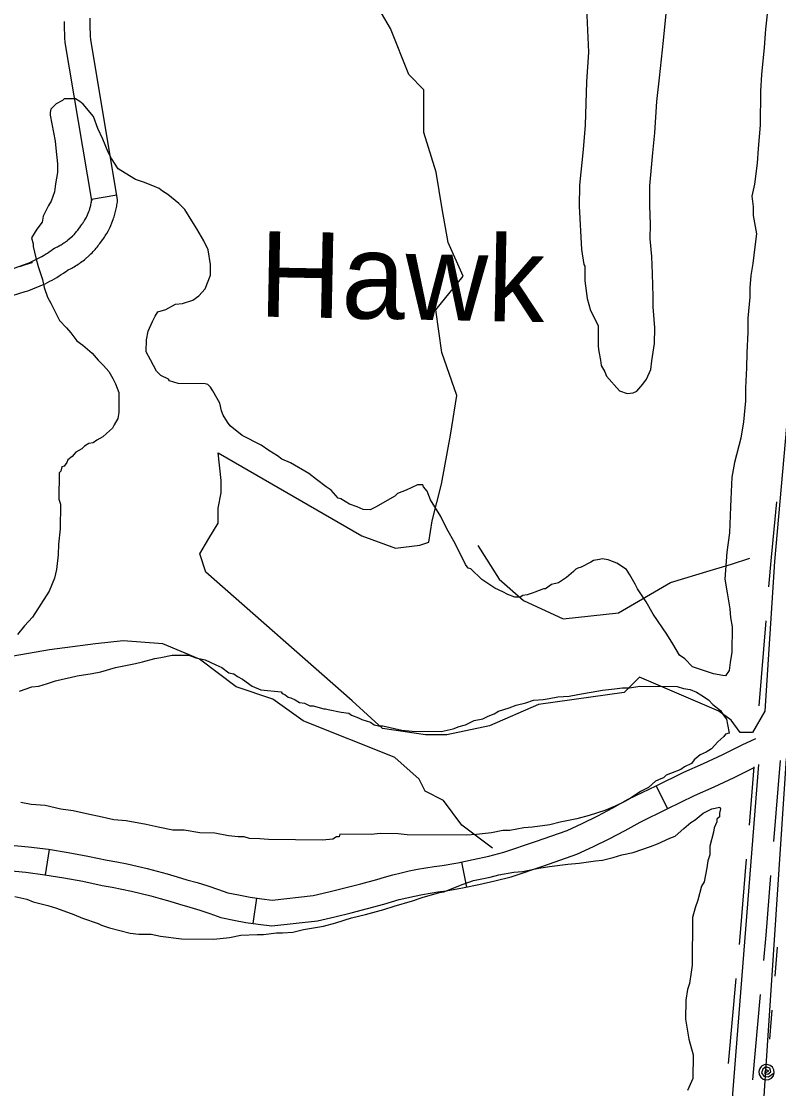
# Model space of a CAD drawing. Extents: x 3172231 to 3210228, y 940198 to 965780.
# Drawn here: x 3181959 to 3182846, y 958356 to 959605 of the extents above; entities that cross this region are included whole.
import ezdxf

# ---------------------------------------------------------------- set-up
doc = ezdxf.new("R2010")
doc.units = 0
for name, color, linetype in [('V-BLDG-IDEN', 7, 'Continuous'), ('V-ROAD-CNTR', 7, 'Continuous'), ('V-SITE-VEGE', 7, 'Continuous'), ('V-TOPO-SHOR', 7, 'Continuous'), ('V-UTIL-LINE', 7, 'Continuous')]:
    doc.layers.add(name, color=color, linetype=linetype)

msp = doc.modelspace()

# ---------------------------------------------------------------- linework, layer by layer
at = {"layer": 'V-ROAD-CNTR'}
for p, q in [((3182041.555, 959396.9), (3182071.146, 959401.841)), ((3182823.248, 958803.608), (3182831.446, 958903.271)), ((3182811.771, 958664.079), (3182817.388, 958732.364)), ((3182840.302, 958644.992), (3182848.114, 958739.96)), ((3182702.78, 958710.235), (3182715.953, 958683.282)), ((3181991.991, 958635.663), (3181987.327, 958606.028)), ((3182474.638, 958620.929), (3182480.562, 958591.52)), ((3182234.916, 958578.761), (3182230.422, 958549.099)), ((3182787.42, 958385.143), (3182796.528, 958484.727)), ((3182815.8, 958366.069), (3182824.908, 958465.653))]:
    msp.add_line(p, q, dxfattribs=at)
for points in [[(3181941.799, 959281.782), (3181964.107, 959288.718), (3181967.069, 959289.698), (3181970.006, 959290.727), (3181972.926, 959291.806), (3181975.83, 959292.938), (3181978.773, 959294.145), (3181984.349, 959296.605), (3181987.229, 959297.965), (3181990.019, 959299.345), (3181992.783, 959300.771), (3181995.53, 959302.249), (3181998.243, 959303.772), (3182000.934, 959305.341), (3182003.597, 959306.962), (3182006.232, 959308.626), (3182008.834, 959310.337), (3182011.403, 959312.088), (3182013.915, 959313.865), (3182013.447, 959313.525), (3182013.656, 959313.624), (3182015.243, 959314.407), (3182016.819, 959315.22), (3182018.383, 959316.062), (3182019.927, 959316.929), (3182021.457, 959317.823), (3182022.972, 959318.745), (3182024.462, 959319.687), (3182025.936, 959320.654), (3182027.405, 959321.654), (3182028.861, 959322.686), (3182030.285, 959323.733), (3182031.69, 959324.803), (3182033.288, 959326.066), (3182039.55, 959331.565), (3182041.001, 959332.984), (3182042.24, 959334.235), (3182043.466, 959335.517), (3182044.671, 959336.823), (3182045.854, 959338.15), (3182047.004, 959339.49), (3182048.129, 959340.844), (3182049.239, 959342.228), (3182050.327, 959343.634), (3182051.384, 959345.054), (3182052.414, 959346.486), (3182053.404, 959347.915), (3182053.321, 959347.792), (3182054.862, 959349.856), (3182055.842, 959351.245), (3182056.755, 959352.589), (3182057.652, 959353.957), (3182058.517, 959355.332), (3182059.394, 959356.774), (3182060.953, 959359.504), (3182061.755, 959360.999), (3182062.5, 959362.447), (3182063.337, 959364.145), (3182066.347, 959371.159), (3182067.001, 959372.932), (3182067.539, 959374.473), (3182068.05, 959376.029), (3182068.531, 959377.583), (3182068.984, 959379.137), (3182069.416, 959380.716), (3182069.818, 959382.307), (3182070.205, 959383.956), (3182070.843, 959387.024), (3182071.141, 959388.687), (3182071.405, 959390.296), (3182071.638, 959391.917), (3182071.835, 959393.472), (3182072.127, 959395.966), (3182040.741, 959583.943), (3182040.5, 959587.59), (3182040.294, 959591.859), (3182040.161, 959596.132), (3182040.102, 959600.401), (3182040.121, 959604.801)], [(3181957.397, 959318.098), (3181959.846, 959318.955), (3181962.276, 959319.854), (3181964.688, 959320.794), (3181967.025, 959321.753), (3181971.889, 959323.897), (3181974.171, 959324.975), (3181976.491, 959326.123), (3181978.799, 959327.313), (3181981.078, 959328.539), (3181983.341, 959329.81), (3181985.578, 959331.115), (3181987.789, 959332.46), (3181989.98, 959333.844), (3181992.144, 959335.267), (3181994.291, 959336.73), (3181996.435, 959338.247), (3181998.087, 959339.447), (3182000.606, 959340.638), (3182001.727, 959341.191), (3182002.833, 959341.762), (3182003.927, 959342.35), (3182005.013, 959342.961), (3182006.093, 959343.591), (3182007.154, 959344.237), (3182008.216, 959344.909), (3182009.264, 959345.596), (3182010.291, 959346.296), (3182011.301, 959347.01), (3182012.309, 959347.753), (3182013.304, 959348.509), (3182014.074, 959349.118), (3182019.15, 959353.577), (3182019.857, 959354.268), (3182020.744, 959355.163), (3182021.602, 959356.059), (3182022.445, 959356.973), (3182023.27, 959357.9), (3182024.086, 959358.85), (3182024.891, 959359.818), (3182025.669, 959360.788), (3182026.427, 959361.77), (3182027.174, 959362.772), (3182027.904, 959363.788), (3182028.634, 959364.841), (3182028.845, 959365.154), (3182030.58, 959367.48), (3182031.178, 959368.327), (3182031.805, 959369.249), (3182032.41, 959370.171), (3182033.003, 959371.114), (3182033.548, 959372.01), (3182034.705, 959374.036), (3182035.197, 959374.953), (3182035.706, 959375.943), (3182036.081, 959376.703), (3182038.469, 959382.267), (3182038.761, 959383.062), (3182039.125, 959384.105), (3182039.47, 959385.151), (3182039.799, 959386.215), (3182040.112, 959387.289), (3182040.402, 959388.352), (3182040.672, 959389.415), (3182040.911, 959390.434), (3182041.387, 959392.728), (3182041.573, 959393.759), (3182041.751, 959394.854), (3182041.908, 959395.941), (3182042.055, 959397.1), (3182041.835, 959395.222), (3182010.905, 959580.475), (3182010.548, 959585.876), (3182010.316, 959590.669), (3182010.167, 959595.46), (3182010.102, 959600.259), (3182010.121, 959604.927)], [(3182040.118, 959604.546), (3182040.208, 959608.816)], [(3181946.867, 959314.473), (3181971.799, 959323.696), (3181971.799, 959322.526), (3181954.939, 959317.284)], [(3182834.725, 958943.137), (3182837.566, 958977.674), (3182843.847, 959042.717)], [(3181929.836, 958642.409), (3181967.912, 958638.792), (3181991.21, 958635.786), (3182014.381, 958632.139), (3182037.44, 958627.855), (3182059.891, 958623.038), (3182071.391, 958621.01), (3182083.263, 958618.686), (3182095.092, 958616.141), (3182106.875, 958613.379), (3182118.605, 958610.394), (3182130.275, 958607.194), (3182141.88, 958603.777), (3182153.049, 958600.264), (3182165.214, 958596.865), (3182177.709, 958593.042), (3182190.104, 958588.911), (3182201.2, 958584.907), (3182213.799, 958582.322), (3182227.339, 958579.909), (3182240.936, 958577.849), (3182253.019, 958576.337), (3182301.27, 958581.648), (3182319.333, 958585.891), (3182338.13, 958590.561), (3182356.866, 958595.471), (3182375.509, 958600.613), (3182384.749, 958603.323), (3182394.324, 958605.907), (3182403.958, 958608.285), (3182413.645, 958610.453), (3182423.374, 958612.41), (3182433.143, 958614.155), (3182442.942, 958615.686), (3182452.319, 958616.943), (3182470.466, 958620.089), (3182488.615, 958623.744), (3182506.653, 958627.89), (3182524.255, 958632.444), (3182561.547, 958644.938), (3182598.488, 958657.913), (3182616.228, 958666.07), (3182634.205, 958674.918), (3182651.939, 958684.235), (3182669.974, 958694.327), (3182702.53, 958710.113), (3182734.89, 958725.928), (3182758.166, 958736.258), (3182780.834, 958746.888), (3182803.529, 958758.11), (3182819.534, 958765.691)], [(3181926.768, 958612.565), (3181964.574, 958608.974), (3181986.958, 958606.086), (3182009.307, 958602.569), (3182031.552, 958598.435), (3182054.137, 958593.59), (3182065.903, 958591.514), (3182077.227, 958589.298), (3182088.512, 958586.871), (3182099.751, 958584.235), (3182110.939, 958581.388), (3182122.071, 958578.336), (3182133.142, 958575.077), (3182144.509, 958571.5), (3182156.788, 958568.071), (3182168.575, 958564.464), (3182180.268, 958560.567), (3182193.052, 958555.953), (3182208.151, 958552.856), (3182222.459, 958550.305), (3182236.826, 958548.129), (3182252.795, 958546.131), (3182306.36, 958552.028), (3182326.381, 958556.729), (3182345.55, 958561.493), (3182364.656, 958566.499), (3182383.721, 958571.757), (3182392.881, 958574.445), (3182401.828, 958576.859), (3182410.83, 958579.081), (3182419.879, 958581.107), (3182428.97, 958582.934), (3182438.097, 958584.565), (3182447.25, 958585.996), (3182456.875, 958587.285), (3182475.992, 958590.599), (3182494.937, 958594.416), (3182513.771, 958598.744), (3182532.787, 958603.664), (3182571.283, 958616.562), (3182609.75, 958630.071), (3182629.12, 958638.978), (3182647.807, 958648.176), (3182666.243, 958657.861), (3182683.856, 958667.717), (3182715.66, 958683.139), (3182747.566, 958698.732), (3182770.62, 958708.964), (3182793.852, 958719.858), (3182816.599, 958731.106), (3182817.142, 958731.363)], [(3182800.171, 958524.561), (3182801.402, 958538.025), (3182808.492, 958624.214)], [(3182828.552, 958505.487), (3182831.29, 958535.429), (3182837.023, 958605.126)]]:
    msp.add_lwpolyline(points, dxfattribs=at)
at = {"layer": 'V-SITE-VEGE'}
for points in [[(3182619.192, 959663.857), (3182623.434, 959569.057), (3182621.085, 959534.436), (3182619.608, 959483.502), (3182617.312, 959454.992), (3182612.862, 959413.256), (3182612.641, 959388.802), (3182615.24, 959337.834), (3182618.14, 959320.487), (3182619.141, 959318.437), (3182618.987, 959301.117), (3182621.859, 959280.713), (3182625.805, 959266.412), (3182634.819, 959249.008), (3182634.599, 959224.557), (3182635.564, 959218.435), (3182637.51, 959208.228), (3182638.472, 959202.107), (3182642.486, 959194.937), (3182644.477, 959189.825), (3182659.603, 959172.366), (3182668.746, 959169.226), (3182675.887, 959170.183), (3182679.981, 959172.183), (3182687.184, 959180.271), (3182691.317, 959186.345), (3182696.51, 959197.509), (3182697.625, 959207.688), (3182700.862, 959228.036), (3182701.026, 959246.376), (3182699.21, 959270.848), (3182699.318, 959283.072), (3182698.538, 959309.569), (3182697.702, 959329.959), (3182695.849, 959350.353), (3182696.005, 959367.673), (3182695.179, 959389.081), (3182695.388, 959412.51), (3182698.794, 959451.203), (3182701.043, 959474.618), (3182703.41, 959511.279), (3182706.714, 959538.759), (3182711.182, 959582.533), (3182714.525, 959614.091)], [(3182833.831, 959624.224), (3182830.517, 959595.724), (3182829.307, 959574.339), (3182825.964, 959542.781), (3182824.773, 959523.432), (3182824.414, 959483.697), (3182822.131, 959456.206), (3182820.955, 959438.894), (3182817.678, 959414.47), (3182814.494, 959400.232), (3182816.421, 959387.989), (3182816.331, 959377.803), (3182820.214, 959356.368), (3182818.037, 959341.102), (3182815.825, 959321.763), (3182813.658, 959307.517), (3182812.511, 959293.263), (3182812.411, 959282.057), (3182810.154, 959257.622), (3182810.006, 959241.32), (3182808.767, 959216.877), (3182808.612, 959199.557), (3182807.383, 959176.132), (3182807.246, 959160.85), (3182804.989, 959136.415), (3182801.755, 959117.084), (3182794.368, 959088.621), (3182791.157, 959071.328), (3182789.907, 959045.865), (3182789.825, 959036.696), (3182788.531, 959006.14), (3182785.273, 958983.753), (3182782.95, 958952.185), (3182785.861, 958935.857), (3182788.752, 958917.488), (3182789.678, 958907.293), (3182791.615, 958896.066), (3182791.351, 958866.519), (3182789.205, 958854.311), (3182788.101, 958845.151), (3182783.972, 958839.074), (3182780.915, 958839.103), (3182769.726, 958841.241), (3182745.347, 958849.611), (3182736.26, 958858.862), (3182730.184, 958862.995), (3182722.151, 958876.313), (3182715.121, 958887.583), (3182699.029, 958911.164), (3182691.007, 958925.502), (3182680.956, 958940.876), (3182677.945, 958946), (3182671.932, 958957.26), (3182667.912, 958963.41), (3182656.771, 958970.644), (3182646.617, 958974.809), (3182639.494, 958975.893), (3182636.428, 958974.902), (3182629.289, 958973.947), (3182626.213, 958971.936), (3182614.951, 958965.923), (3182610.865, 958964.942), (3182608.819, 958963.941), (3182605.735, 958960.912), (3182597.52, 958953.854), (3182588.296, 958947.823), (3182580.127, 958945.859), (3182572.948, 958940.829), (3182570.911, 958940.847), (3182568.865, 958939.846), (3182565.799, 958938.855), (3182560.685, 958936.862), (3182558.639, 958935.863), (3182551.487, 958933.888), (3182546.386, 958932.916), (3182543.31, 958930.906), (3182537.196, 958930.962), (3182529.074, 958934.091), (3182522.987, 958937.2), (3182513.855, 958941.359), (3182498.663, 958951.685), (3182485.53, 958964.033), (3182482.48, 958965.077), (3182479.461, 958969.182), (3182467.456, 958993.743), (3182457.423, 959011.155), (3182450.419, 959025.483), (3182438.366, 959044.951), (3182434.383, 959055.177)], [(3182434.383, 959055.177), (3182430.354, 959060.307), (3182429.353, 959062.355), (3182423.24, 959062.411), (3182409.94, 959056.416), (3182399.714, 959052.433), (3182396.632, 959049.404), (3182374.098, 959036.36), (3182367.958, 959033.358), (3182359.805, 959033.431), (3182352.7, 959036.553), (3182343.558, 959039.69), (3182333.423, 959045.896), (3182330.377, 959046.94), (3182322.308, 959056.185), (3182316.234, 959060.316), (3182305.099, 959068.567), (3182295.993, 959075.782), (3182274.706, 959088.201), (3182264.554, 959092.369), (3182259.498, 959096.489), (3182249.364, 959102.695), (3182240.251, 959108.89), (3182217.936, 959120.297), (3182203.774, 959131.631), (3182200.751, 959135.737), (3182195.731, 959143.933), (3182193.741, 959149.045), (3182191.785, 959158.234), (3182188.774, 959163.357), (3182183.763, 959172.57), (3182180.744, 959176.675), (3182177.713, 959179.759), (3182174.666, 959180.808), (3182143.081, 959181.088), (3182132.919, 959184.238), (3182131.92, 959186.284), (3182122.788, 959190.441), (3182117.737, 959195.582), (3182110.723, 959208.892), (3182105.716, 959218.108), (3182105.843, 959232.37), (3182107.971, 959242.54), (3182113.166, 959253.702), (3182116.277, 959259.789), (3182119.382, 959264.855), (3182128.577, 959267.829), (3182139.839, 959273.84), (3182147.999, 959274.786), (3182160.262, 959278.751), (3182167.44, 959283.781), (3182174.645, 959291.869), (3182180.906, 959308.115), (3182181.017, 959320.342), (3182178.115, 959337.69), (3182173.113, 959347.924), (3182165.089, 959362.26), (3182159.06, 959371.487), (3182151.028, 959384.805), (3182143.96, 959392.001), (3182130.806, 959402.309), (3182124.729, 959406.44), (3182120.682, 959409.532), (3182113.578, 959412.653), (3182102.406, 959416.829), (3182093.266, 959419.969), (3182081.103, 959427.211), (3182072.999, 959432.378), (3182064.956, 959444.678), (3182060.946, 959451.844), (3182054.97, 959467.183), (3182048.968, 959479.465), (3182044.001, 959493.775), (3182031.904, 959508.146), (3182027.855, 959511.242), (3182022.788, 959514.345), (3182009.542, 959514.464), (3182007.487, 959512.444), (3182000.319, 959508.432), (3181994.151, 959502.374), (3181993.094, 959498.309), (3181993.067, 959495.251), (3181998.906, 959464.632), (3181999.85, 959456.47), (3182001.724, 959438.112), (3182001.632, 959427.925), (3181999.476, 959414.697), (3181998.374, 959405.539), (3181994.198, 959394.367), (3181991.095, 959389.3), (3181984.871, 959377.129), (3181983.79, 959370.006), (3181977.603, 959361.91), (3181971.398, 959351.777), (3181973.372, 959344.625), (3181973.343, 959341.567), (3181976.28, 959328.296), (3181979.243, 959318.081), (3181984.204, 959302.754), (3181986.158, 959293.564), (3181990.133, 959282.321)], [(3181990.133, 959282.321), (3181994.145, 959275.153), (3182004.149, 959254.683), (3182012.229, 959246.458), (3182017.269, 959240.3), (3182024.316, 959231.065), (3182031.4, 959225.909), (3182042.527, 959216.637), (3182049.584, 959208.423), (3182055.642, 959202.254), (3182061.692, 959195.068), (3182066.714, 959186.872), (3182069.716, 959180.73), (3182073.699, 959170.504), (3182073.488, 959147.071), (3182072.403, 959139.948), (3182068.266, 959132.854), (3182066.191, 959128.797), (3182059.005, 959122.747), (3182054.892, 959118.708), (3182047.722, 959114.696), (3182043.62, 959111.677), (3182038.517, 959110.705), (3182033.395, 959107.694), (3182030.31, 959104.665), (3182023.14, 959100.653), (3182019.022, 959095.594), (3182013.889, 959091.566), (3182012.845, 959088.519), (3182009.75, 959084.472), (3182006.685, 959083.478), (3182005.62, 959078.393), (3182003.563, 959076.376), (3182003.289, 959045.81), (3182005.271, 959039.678), (3182005.015, 959011.149), (3182002.812, 958992.83), (3182002.701, 958980.603), (3182000.51, 958963.3), (3181998.38, 958953.129), (3181992.129, 958937.902), (3181972.495, 958907.51), (3181963.234, 958897.405), (3181954.991, 958887.29)], [(3181957.453, 958821.037), (3181971.762, 958826.004), (3181979.921, 958826.948), (3181990.139, 958829.913), (3181999.336, 958832.887), (3182007.506, 958834.851), (3182016.693, 958836.807), (3182024.863, 958838.771), (3182042.209, 958841.671), (3182052.416, 958843.619), (3182069.783, 958848.556), (3182093.264, 958853.441), (3182101.431, 958855.403), (3182115.732, 958859.351), (3182122.874, 958860.306), (3182136.147, 958863.243), (3182155.505, 958863.066), (3182163.629, 958859.939), (3182174.817, 958857.801), (3182186.988, 958851.577), (3182194.093, 958848.454), (3182202.189, 958842.271), (3182208.292, 958841.198), (3182212.341, 958838.103), (3182218.425, 958834.993), (3182229.558, 958826.739), (3182239.712, 958822.573)], [(3182239.712, 958822.573), (3182263.717, 958820.233), (3182264.716, 958818.185), (3182267.764, 958817.138), (3182271.813, 958814.046), (3182274.86, 958813.001), (3182279.935, 958810.914), (3182285.002, 958807.813), (3182291.107, 958806.738), (3182297.193, 958803.627), (3182301.267, 958803.591), (3182313.467, 958800.424), (3182315.5, 958800.406), (3182318.552, 958799.359), (3182333.806, 958796.167), (3182342.968, 958795.065), (3182346.005, 958792.998), (3182354.128, 958789.869), (3182358.185, 958787.794), (3182368.343, 958784.647), (3182372.394, 958781.552), (3182377.479, 958780.489), (3182382.575, 958780.442), (3182404.943, 958775.148), (3182417.159, 958774.017), (3182450.781, 958773.716), (3182465.072, 958776.645), (3182472.234, 958779.635), (3182479.383, 958781.609), (3182489.617, 958786.613), (3182499.825, 958788.558), (3182505.964, 958791.561), (3182513.124, 958794.553), (3182518.246, 958797.563), (3182530.51, 958801.528), (3182538.687, 958804.512), (3182549.923, 958807.467), (3182559.118, 958810.441), (3182570.335, 958811.361), (3182577.475, 958812.315), (3182587.684, 958814.261), (3182600.938, 958815.16), (3182611.146, 958817.105), (3182639.719, 958821.947), (3182654, 958823.855), (3182663.179, 958824.789), (3182671.33, 958824.716), (3182683.575, 958826.645), (3182727.386, 958826.25), (3182734.501, 958824.148), (3182742.642, 958823.057), (3182749.746, 958819.936), (3182754.813, 958816.833), (3182763.926, 958810.638), (3182768.977, 958805.497), (3182778.08, 958798.282), (3182781.093, 958793.16), (3182785.121, 958788.03), (3182786.086, 958781.906), (3182788.031, 958771.699), (3182783.948, 958770.718), (3182781.881, 958767.681), (3182774.695, 958761.631), (3182767.49, 958753.544), (3182761.34, 958749.523), (3182754.18, 958746.531), (3182746.994, 958740.483), (3182743.899, 958736.435), (3182735.711, 958732.433), (3182731.609, 958729.414), (3182726.497, 958727.421), (3182724.449, 958726.42), (3182714.226, 958722.436), (3182711.141, 958719.407), (3182708.075, 958718.416), (3182701.934, 958715.416), (3182693.719, 958708.356), (3182684.501, 958703.345), (3182672.205, 958695.303), (3182665.037, 958691.293), (3182654.799, 958686.289), (3182642.529, 958681.304), (3182624.134, 958675.357), (3182609.835, 958671.413), (3182590.438, 958667.509), (3182578.185, 958664.562), (3182557.781, 958661.691), (3182547.584, 958660.763), (3182531.255, 958657.853), (3182523.102, 958657.924), (3182509.831, 958654.988), (3182492.493, 958653.106), (3182480.258, 958652.196), (3182410.974, 958652.821), (3182400.796, 958653.931), (3182379.398, 958654.123), (3182369.201, 958653.196), (3182332.523, 958653.525), (3182331.477, 958650.48), (3182328.419, 958650.509), (3182324.317, 958647.486)], [(3181951.802, 958580.531), (3181966.04, 958577.346), (3181973.145, 958574.225), (3181990.43, 958569.994), (3182000.59, 958566.846), (3182020.902, 958559.53), (3182031.054, 958555.365), (3182049.338, 958549.086), (3182053.395, 958547.011), (3182062.538, 958543.871), (3182086.935, 958537.539), (3182097.114, 958536.429), (3182111.378, 958536.3), (3182122.567, 958534.162), (3182146.991, 958530.885), (3182184.691, 958530.545), (3182203.047, 958532.419), (3182216.318, 958535.356), (3182235.688, 958536.202), (3182242.819, 958536.136), (3182258.122, 958538.037), (3182265.253, 958537.973), (3182277.488, 958538.882), (3182289.743, 958541.827), (3182313.213, 958545.692), (3182327.512, 958549.641), (3182345.907, 958555.59), (3182362.244, 958559.516), (3182383.697, 958565.437), (3182395.956, 958569.404), (3182417.411, 958575.322), (3182428.655, 958579.298), (3182449.085, 958585.229), (3182454.189, 958586.201), (3182476.686, 958595.17), (3182488.95, 958599.135), (3182508.344, 958603.034), (3182518.562, 958605.999), (3182535.908, 958608.901), (3182546.103, 958609.827), (3182565.502, 958613.731), (3182577.747, 958615.658), (3182599.169, 958618.521), (3182612.424, 958619.42), (3182631.808, 958622.304), (3182639.969, 958623.25), (3182652.222, 958626.197), (3182662.44, 958629.16), (3182675.711, 958632.097), (3182696.152, 958639.046), (3182704.334, 958642.03), (3182718.66, 958649.032), (3182724.791, 958651.017), (3182735.062, 958660.093), (3182743.276, 958667.153), (3182748.399, 958670.163), (3182757.641, 958678.232), (3182767.875, 958683.234), (3182777.066, 958685.189), (3182778.064, 958683.144), (3182776.999, 958678.058), (3182776.962, 958673.983), (3182773.88, 958670.954), (3182773.851, 958667.896), (3182770.732, 958660.792), (3182769.667, 958655.706), (3182765.444, 958639.441), (3182765.352, 958629.252), (3182763.251, 958622.14)], [(3182324.317, 958647.486), (3182312.082, 958646.577), (3182248.912, 958647.146), (3182238.733, 958648.256), (3182226.507, 958648.366), (3182220.412, 958650.46), (3182213.281, 958650.523), (3182202.082, 958651.643), (3182185.809, 958654.846), (3182168.489, 958655.002), (3182150.176, 958658.223), (3182136.931, 958658.342), (3182119.638, 958661.556), (3182105.4, 958664.74), (3182082.004, 958669.027), (3182067.75, 958670.174), (3182050.467, 958674.405), (3182039.276, 958676.543), (3182019.956, 958680.792), (3182005.71, 958682.959), (3181987.407, 958687.199), (3181971.115, 958688.366), (3181958.909, 958690.512)], [(3182763.251, 958622.14), (3182762.157, 958613.999), (3182758.956, 958597.724), (3182755.851, 958592.657), (3182751.63, 958576.392), (3182748.491, 958567.249), (3182745.335, 958556.069), (3182744.831, 958500.034), (3182743.737, 958491.893), (3182741.581, 958478.665), (3182739.479, 958471.55), (3182737.331, 958459.342), (3182737.13, 958436.929), (3182740.995, 958413.459), (3182745.923, 958395.074), (3182745.677, 958367.563), (3182739.434, 958353.354)]]:
    msp.add_lwpolyline(points, dxfattribs=at)
at = {"layer": 'V-TOPO-SHOR'}
for points in [[(3182870.515, 959302.084), (3182841.069, 958972.891), (3182829.899, 958797.548), (3182815.521, 958772.531), (3182801.205, 958772.567), (3182790.504, 958786.909), (3182776.215, 958797.681), (3182683.259, 958837.28), (3182665.32, 958819.429), (3182565.074, 958805.361), (3182507.749, 958780.45), (3182457.617, 958769.837), (3182432.564, 958769.899), (3182382.477, 958777.181), (3182346.767, 958809.48), (3182175.349, 958960.221), (3182168.244, 958981.712), (3182179.025, 958999.58), (3182189.806, 959017.449), (3182189.85, 959035.343), (3182193.473, 959053.229), (3182193.509, 959067.545), (3182190.009, 959099.765), (3182357.981, 959002.717), (3182397.314, 958988.304), (3182425.955, 958991.812), (3182436.701, 958995.364), (3182440.342, 959020.408), (3182451.185, 959063.329), (3182462.063, 959120.566), (3182469.336, 959167.075), (3182451.565, 959217.224), (3182444.531, 959267.347), (3182476.839, 959306.636), (3182459.042, 959346.049), (3182451.981, 959385.435), (3182444.929, 959428.4), (3182430.729, 959474.962), (3182430.853, 959525.067), (3182413.002, 959543.006), (3182391.661, 959596.744), (3182380.968, 959614.665)], [(3182493.955, 958991.644), (3182518.91, 958952.213), (3182547.48, 958927.09), (3182593.953, 958905.501), (3182658.392, 958912.5), (3182719.323, 958948.139), (3182765.885, 958962.34), (3182790.955, 958969.436), (3182812.447, 958976.54)], [(3182510.974, 958637.283), (3182475.251, 958664.214), (3182453.848, 958692.898), (3182432.401, 958703.688), (3182425.278, 958718.022), (3182396.708, 958743.145), (3182360.954, 958757.55), (3182325.2, 958771.954), (3182289.446, 958786.358), (3182253.718, 958811.5), (3182210.806, 958825.922), (3182167.938, 958858.238), (3182125.035, 958876.239), (3182078.518, 958879.933), (3182046.298, 958876.434), (3181992.596, 958869.409), (3181931.727, 958858.822)], [(3182854.814, 958742.013), (3182813.915, 958122.951), (3182777.055, 957689.986), (3182747.671, 957385.846), (3182706.807, 956781.1), (3182688.275, 956523.459), (3182666.5, 956401.828)], [(3182822.586, 958734.934), (3182778.258, 958176.724), (3182737.969, 957804.61), (3182723.193, 957618.54), (3182682.4, 957042.425), (3182656.684, 956774.066), (3182574.359, 956770.69), (3182484.885, 956770.911), (3182427.604, 956763.895), (3182381.104, 956774.747), (3182352.49, 956781.976)]]:
    msp.add_lwpolyline(points, dxfattribs=at)
at = {"layer": 'V-UTIL-LINE'}
for points in [[(3182844.484, 958521.353), (3182841.59, 958487.476)], [(3182838.186, 958447.621), (3182835.292, 958413.744)], [(3182831.973, 958374.896), (3182834.47, 958376.325), (3182832.365, 958377.316), (3182830.017, 958375.892), (3182830.092, 958372.965), (3182833.46, 958372.515), (3182837.118, 958375.448), (3182835.677, 958379.464), (3182831.116, 958381.152), (3182827.472, 958378.38), (3182826.134, 958374.115), (3182828.878, 958370.148), (3182834.327, 958369.358), (3182840.941, 958374.13), (3182840.551, 958377.619), (3182838.856, 958380.695), (3182836.113, 958382.887), (3182832.739, 958383.863), (3182829.25, 958383.474), (3182826.174, 958381.778), (3182823.982, 958379.035), (3182823.006, 958375.662), (3182823.395, 958372.172), (3182825.091, 958369.096), (3182827.834, 958366.904), (3182831.207, 958365.928), (3182834.697, 958366.318), (3182837.773, 958368.013), (3182839.965, 958370.756), (3182840.941, 958374.13)]]:
    msp.add_lwpolyline(points, dxfattribs=at)

# ---------------------------------------------------------------- texts
at = {"layer": 'V-BLDG-IDEN'}
msp.add_text('Hawk', height=99.9998, rotation=358.874298, dxfattribs=at).set_placement((3182237.104, 959259.503))

doc.saveas('drawing.dxf')
